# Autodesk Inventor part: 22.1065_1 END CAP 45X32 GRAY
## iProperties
Created: 2007-01
Part Number: 22.1065_1 END CAP 45X32 GRAY
Document SubType Name: Modeling
Designer: Andy Moles
Material: ABS Plastic
Density: 1.06 g/cm^3
Mass: 4.49949 g
Surface Area: 32.3589 cm^2
Volume: 4.2448 cm^3
Author: Andy Moles
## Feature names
1. Extrusion1
2. Fillet1
3. Fillet2
4. Extrusion2
5. Fillet3
